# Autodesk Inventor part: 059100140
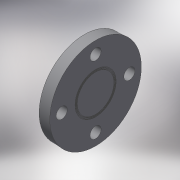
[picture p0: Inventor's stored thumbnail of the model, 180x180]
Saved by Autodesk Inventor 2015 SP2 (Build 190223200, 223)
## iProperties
Created: 2017-10
Part Number: 059100140
Material: Generic
Description: PLASSON BLANK FLANGE PVC 140
Document SubType Name: Modeling
Designer: KIM
Density: 1 g/cm^3
Appearance: Default
Author: KIM
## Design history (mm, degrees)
derived "059100.ipt"
feature "Solid1::059100.ipt"
tag "TaggingFeature1"
body "Solid1"
other parameters: "d0" = 28, "d3" = 247.5, "d12" = 45 deg, "d14" = 18, "d15" = 105.5, "d16" = 28, "d17" = 0, "d19" = 360 deg, "d21" = 1.25, "d22" = 1.25, "d23" = 1.25, "d24" = 1.25, "d25" = 1.25, "d26" = 0.5, "d27" = 0, "H_" = 28, "Dp_" = 211, "S_" = 18
